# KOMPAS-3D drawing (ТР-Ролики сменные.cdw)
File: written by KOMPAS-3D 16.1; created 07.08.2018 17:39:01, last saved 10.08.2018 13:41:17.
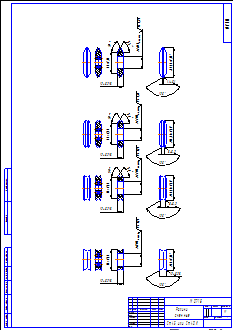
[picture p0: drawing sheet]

Sheet 1: A2, portrait

Title block, sheet 1: name: Ролики / сменные; designation: М0718; material: Ст45 или Ст40Х; scale: 1:1; sheets: 1; sheet format: A2; stored path: C:\Users\User\Desktop\Станки\Малый 0718\ТР-Ролик вертикальный.cdw

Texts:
  User
  Ra 1,25
  Стандартные изделия
  Подшипник 4А-1060900 ГОСТ 10058-90
  Подшипник
  ГОСТ 10058-90
Dimensions and other numbers on the sheet: 38±0,31; 12±0,215; 22; 8±0,2; 43,93±0,31; 120; 5±0,2; 48,38±0,31; 54,96±0,37; 1,4±0,1; 4А-1060900; 1:1; 1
